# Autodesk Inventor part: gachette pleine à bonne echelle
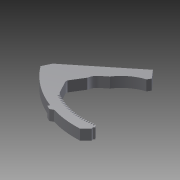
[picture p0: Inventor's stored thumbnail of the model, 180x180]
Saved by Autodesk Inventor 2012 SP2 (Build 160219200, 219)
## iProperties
Created: 2013-11
Part Number: gachette pleine à bonne echelle
Material: Default
Document SubType Name: Modeling
Designer: Administrateur
Density: 1 g/cm^3
Author: Administrateur
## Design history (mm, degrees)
derived "gachette pleine.ipt" dims "d0" = 1.90476
feature "Solide1::gachette pleine.ipt" dims "d0" = 1.90476
tag "FonctionRepérage1"
node "Solide1"
